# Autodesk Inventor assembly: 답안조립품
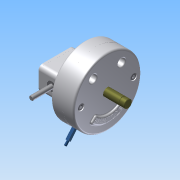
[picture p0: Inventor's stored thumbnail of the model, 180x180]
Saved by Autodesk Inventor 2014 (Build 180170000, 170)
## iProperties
Created: 2015-04
Part Number: 답안조립품
Document SubType Name: Assembly
Designer: Administrator
Author: Administrator
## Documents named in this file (15)
- C:\Documents and Settings\Administrator\바탕 화면\350406V1042\답안조립품.iam
- C:\Documents and Settings\Administrator\바탕 화면\350406V1042\본체.ipt
- C:\Documents and Settings\Administrator\바탕 화면\350406V1042\커버.ipt
- C:\Documents and Settings\Administrator\바탕 화면\350406V1042\베어링62_22.ipt
- C:\Documents and Settings\Administrator\바탕 화면\350406V1042\축.ipt
- C:\Documents and Settings\Administrator\바탕 화면\350406V1042\멈춤링.ipt
- C:\Documents and Settings\Administrator\바탕 화면\350406V1042\슬라이더2.ipt
- C:\Documents and Settings\Administrator\바탕 화면\350406V1042\슬라이더.ipt
- C:\Documents and Settings\Administrator\바탕 화면\350406V1042\평행핀.ipt
- C:\Documents and Settings\Administrator\바탕 화면\350406V1042\부시.ipt
- C:\Documents and Settings\Administrator\바탕 화면\350406V1042\슬라이더3.ipt
- C:\Documents and Settings\Administrator\바탕 화면\350406V1042\스프링-[가변].ipt
- C:\Documents and Settings\Administrator\바탕 화면\350406V1042\커버2.ipt
- C:\Documents and Settings\Administrator\바탕 화면\350406V1042\M 10 x 35.ipt
- C:\Documents and Settings\Administrator\바탕 화면\350406V1042\M 5 x 12.ipt
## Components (5 placed, 3 different names)
1. KS B 1320 B B 5 x  20:1
2. M 10 x 35:1
3. M 10 x 35:2
4. M 5 x 12:1
5. M 5 x 12:2
